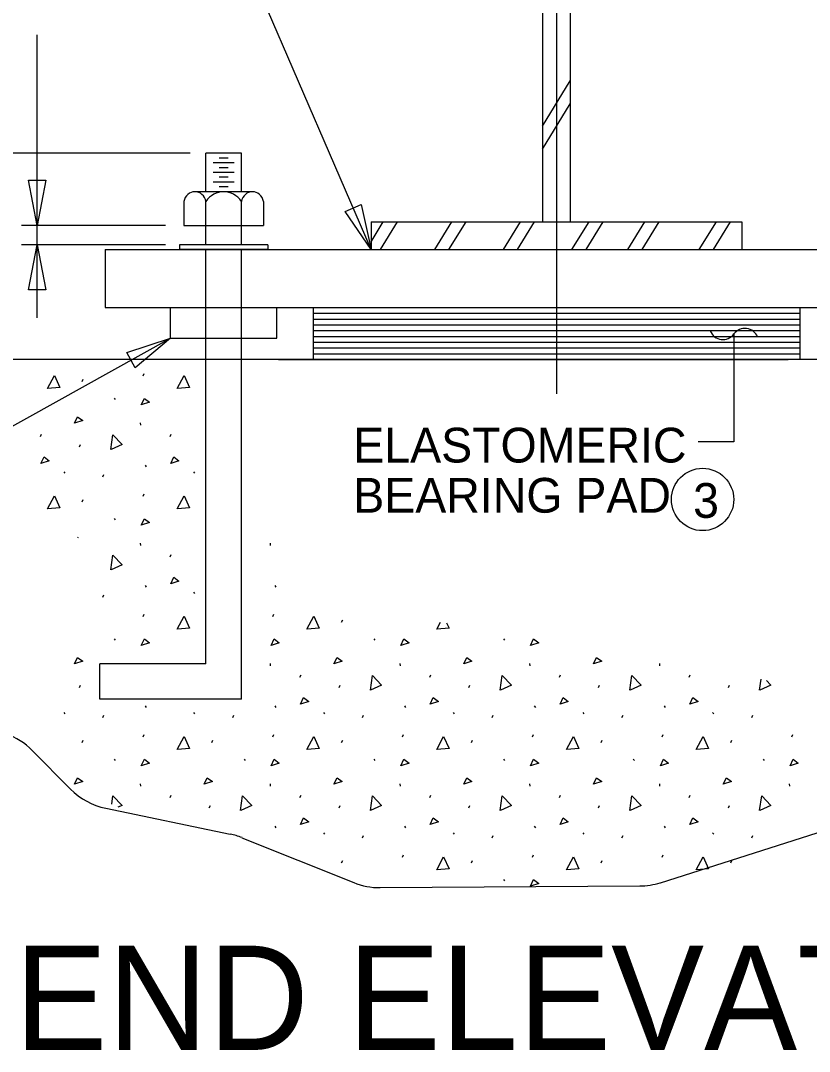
# Model space of a CAD drawing. Extents: x -125.5 to -89.4, y -5.1 to 16.9.
# Drawn here: x -118.408 to -115.571, y 10.484 to 14.192 of the extents above; entities that cross this region are included whole.
import ezdxf

# ---------------------------------------------------------------- set-up
doc = ezdxf.new("R2010")
doc.units = 0
for name, color, linetype in [('BR_AUTO DIMENSION', 7, 'Continuous'), ('BR_CENTER LINES', 7, 'Continuous'), ('BR_CONCRETE', 7, 'Continuous'), ('BR_REBAR', 7, 'Continuous'), ('BR_STRUCTURAL STEEL', 7, 'Continuous'), ('BR_TEXT', 7, 'Continuous'), ('Default', 7, 'Continuous')]:
    doc.layers.add(name, color=color, linetype=linetype)

msp = doc.modelspace()

# ---------------------------------------------------------------- linework, layer by layer
at = {"layer": 'BR_AUTO DIMENSION'}
for p, q in [((-117.1478, 13.3682), (-118.1091, 15.5991)), ((-118.3489, 13.1223), (-118.3489, 14.1408)), ((-117.7986, 13.7148), (-118.8938, 13.7148)), ((-117.8876, 13.4549), (-118.4049, 13.4549)), ((-117.8876, 13.3855), (-118.4049, 13.3855)), ((-115.8429, 13.0645), (-115.8429, 12.6766)), ((-119.3102, 12.2479), (-117.8689, 13.0491)), ((-115.8429, 12.6766), (-115.9716, 12.6766))]:
    msp.add_line(p, q, dxfattribs=at)
for points in [[(-118.3176, 13.6174), (-118.3489, 13.4549), (-118.3801, 13.6174)], [(-117.1834, 13.5298), (-117.1478, 13.3682), (-117.2408, 13.5051)], [(-118.3801, 13.223), (-118.3489, 13.3855), (-118.3176, 13.223)], [(-118.0261, 12.9975), (-117.8689, 13.0491), (-117.9957, 12.9429)]]:
    msp.add_lwpolyline(points, close=True, dxfattribs=at)
msp.add_circle((-115.9555, 12.4692), 0.1121, dxfattribs=at)
for centre, start, end in [((-115.8824, 13.0932), 201.5249, 323.9891), ((-115.8035, 13.0358), 21.5249, 143.9891)]:
    msp.add_arc(centre, 0.0488, start, end, dxfattribs=at)
at = {"layer": 'BR_CENTER LINES'}
msp.add_line((-116.4811, 15.9412), (-116.4811, 12.8489), dxfattribs=at)
at = {"layer": 'BR_CONCRETE'}
msp.add_line((-114.1549, 12.9727), (-119.7474, 12.9727), dxfattribs=at)
at = {"layer": 'BR_REBAR'}
for p, q in [((-117.6141, 13.7148), (-117.7415, 13.7148)), ((-117.7415, 13.5762), (-117.7415, 13.7148)), ((-117.6619, 13.6975), (-117.6937, 13.6975)), ((-117.6141, 13.5762), (-117.6141, 13.7148)), ((-117.6396, 13.6802), (-117.716, 13.6802)), ((-117.6619, 13.6628), (-117.6937, 13.6628)), ((-117.6396, 13.6455), (-117.716, 13.6455)), ((-117.6396, 13.6109), (-117.716, 13.6109)), ((-117.6619, 13.6282), (-117.6937, 13.6282)), ((-117.5743, 13.5762), (-117.7813, 13.5762)), ((-117.6619, 13.5935), (-117.6937, 13.5935)), ((-117.8211, 13.5415), (-117.8211, 13.4549)), ((-117.7415, 13.3855), (-117.7415, 13.5415)), ((-117.6141, 13.3855), (-117.6141, 13.5415)), ((-117.5345, 13.5415), (-117.5345, 13.4549)), ((-117.8211, 13.4549), (-117.5345, 13.4549)), ((-117.837, 13.3855), (-117.837, 13.3682)), ((-117.5185, 13.3855), (-117.837, 13.3855)), ((-117.5185, 13.3682), (-117.837, 13.3682)), ((-117.7415, 13.1599), (-117.7415, 13.3682)), ((-117.6141, 13.1599), (-117.6141, 13.3682)), ((-117.5185, 13.3855), (-117.5185, 13.3682)), ((-117.7415, 12.9727), (-117.7415, 13.1599)), ((-117.6141, 12.9727), (-117.6141, 13.1599)), ((-117.7415, 11.8779), (-117.7415, 12.9727)), ((-117.6141, 11.7505), (-117.6141, 12.9727)), ((-118.1234, 11.7505), (-118.1234, 11.8779)), ((-117.7415, 11.8779), (-118.1234, 11.8779)), ((-117.6141, 11.7505), (-118.1234, 11.7505))]:
    msp.add_line(p, q, dxfattribs=at)
for centre, major_axis, start_param, end_param in [((-117.7813, 13.5318), (0, 0.0444), 4.933703, 7.632667), ((-117.6778, 13.4895), (0, 0.0867), 5.35589, 7.210481), ((-117.5743, 13.5318), (0, 0.0444), 4.933703, 7.632667)]:
    msp.add_ellipse(centre, major_axis=major_axis, ratio=0.918783, start_param=start_param, end_param=end_param, dxfattribs=at)
at = {"layer": 'BR_STRUCTURAL STEEL'}
for p, q in [((-116.5311, 15.4006), (-116.5311, 13.4682)), ((-116.4311, 15.3403), (-116.4311, 13.4682)), ((-116.5311, 13.8126), (-116.4311, 13.9757)), ((-116.5311, 13.7298), (-116.4311, 13.8929)), ((-117.1478, 13.4682), (-115.8144, 13.4682)), ((-117.1478, 13.4682), (-117.1478, 13.3682)), ((-117.1478, 13.3963), (-117.1037, 13.4682)), ((-117.1143, 13.3682), (-117.0529, 13.4682)), ((-116.9184, 13.3682), (-116.8571, 13.4682)), ((-116.8677, 13.3682), (-116.8063, 13.4682)), ((-116.6718, 13.3682), (-116.6105, 13.4682)), ((-116.621, 13.3682), (-116.5597, 13.4682)), ((-116.4252, 13.3682), (-116.3638, 13.4682)), ((-116.3744, 13.3682), (-116.3131, 13.4682)), ((-116.224, 13.3682), (-116.1627, 13.4682)), ((-116.1732, 13.3682), (-116.1119, 13.4682)), ((-115.9672, 13.3682), (-115.9059, 13.4682)), ((-115.9164, 13.3682), (-115.8551, 13.4682)), ((-115.8144, 13.4682), (-115.8144, 13.3682)), ((-118.1036, 13.3682), (-114.8585, 13.3682)), ((-118.1036, 13.3682), (-118.1036, 13.1599)), ((-117.1478, 13.3682), (-115.8144, 13.3682)), ((-118.1036, 13.1599), (-114.8585, 13.1599)), ((-117.8689, 13.0491), (-117.8689, 13.1599)), ((-117.4867, 13.0491), (-117.4867, 13.1599)), ((-117.3561, 13.1599), (-117.3561, 12.9727)), ((-117.3561, 13.1391), (-115.6061, 13.1391)), ((-115.6061, 13.1599), (-115.6061, 12.9727)), ((-117.3561, 13.1183), (-115.6061, 13.1183)), ((-117.3561, 13.0975), (-115.6061, 13.0975)), ((-117.3561, 13.0767), (-115.6061, 13.0767)), ((-117.3561, 13.0559), (-115.6061, 13.0559)), ((-117.8689, 13.0491), (-117.4867, 13.0491)), ((-117.3561, 13.0351), (-115.6061, 13.0351)), ((-117.3561, 13.0143), (-115.6061, 13.0143)), ((-117.3561, 12.9935), (-115.6061, 12.9935))]:
    msp.add_line(p, q, dxfattribs=at)
at = {"layer": 'Default'}
for p, q in [((-117.3561, 13.1599), (-115.6061, 13.1599)), ((-117.4811, 12.9727), (-115.6478, 12.9727)), ((-118.3117, 12.8681), (-118.2868, 12.9153)), ((-118.2868, 12.9153), (-118.2673, 12.8718)), ((-117.9676, 12.9144), (-117.9639, 12.9227)), ((-117.8451, 12.8681), (-117.8201, 12.9153)), ((-117.8201, 12.9153), (-117.8007, 12.8718)), ((-118.2673, 12.8718), (-118.3108, 12.8681)), ((-118.1869, 12.8931), (-118.1831, 12.9014)), ((-117.8007, 12.8718), (-117.8441, 12.8681)), ((-118.0712, 12.8339), (-118.0675, 12.8283)), ((-117.9741, 12.8098), (-117.963, 12.833)), ((-117.963, 12.833), (-117.9445, 12.8191)), ((-117.9445, 12.8191), (-117.9741, 12.8098)), ((-118.2144, 12.7437), (-118.2033, 12.7668)), ((-118.2033, 12.7668), (-118.1848, 12.753)), ((-118.1848, 12.753), (-118.2144, 12.7437)), ((-117.9777, 12.7452), (-117.9768, 12.7368)), ((-118.3367, 12.6961), (-118.333, 12.7044)), ((-118.0836, 12.6486), (-118.0762, 12.7014)), ((-118.0762, 12.7014), (-118.0431, 12.6672)), ((-117.87, 12.6961), (-117.8663, 12.7044)), ((-118.1961, 12.6581), (-118.1924, 12.6665)), ((-118.0431, 12.6672), (-118.0827, 12.6489)), ((-118.3349, 12.5989), (-118.3238, 12.6221)), ((-118.3053, 12.6082), (-118.3349, 12.5989)), ((-118.3238, 12.6221), (-118.3053, 12.6082)), ((-117.8682, 12.5989), (-117.8571, 12.6221)), ((-117.8386, 12.6082), (-117.8682, 12.5989)), ((-117.8571, 12.6221), (-117.8386, 12.6082)), ((-117.9606, 12.5925), (-117.9569, 12.5869)), ((-118.2527, 12.5689), (-118.249, 12.5634)), ((-118.1119, 12.5508), (-118.1082, 12.5592)), ((-117.786, 12.5689), (-117.7823, 12.5634)), ((-118.3117, 12.4353), (-118.2868, 12.4824)), ((-118.2868, 12.4824), (-118.2673, 12.439)), ((-118.1869, 12.4602), (-118.1831, 12.4686)), ((-117.9676, 12.4815), (-117.9639, 12.4898)), ((-117.8451, 12.4353), (-117.8201, 12.4824)), ((-117.8201, 12.4824), (-117.8007, 12.439)), ((-118.2673, 12.439), (-118.3108, 12.4353)), ((-117.8007, 12.439), (-117.8441, 12.4353)), ((-118.0712, 12.401), (-118.0675, 12.3955)), ((-117.9741, 12.377), (-117.963, 12.4001)), ((-117.9445, 12.3862), (-117.9741, 12.377)), ((-117.963, 12.4001), (-117.9445, 12.3862)), ((-118.2037, 12.3332), (-118.2033, 12.334)), ((-118.2033, 12.334), (-118.2014, 12.3326)), ((-117.9777, 12.3123), (-117.9768, 12.304)), ((-117.511, 12.3123), (-117.5101, 12.304)), ((-118.0836, 12.2157), (-118.0762, 12.2686)), ((-118.0762, 12.2686), (-118.0431, 12.2344)), ((-117.87, 12.2632), (-117.8663, 12.2715)), ((-118.0431, 12.2344), (-118.0827, 12.216)), ((-117.8682, 12.1661), (-117.8571, 12.1892)), ((-117.8386, 12.1753), (-117.8682, 12.1661)), ((-117.8571, 12.1892), (-117.8386, 12.1753)), ((-118.1119, 12.118), (-118.1082, 12.1263)), ((-117.9606, 12.1596), (-117.9569, 12.1541)), ((-117.786, 12.1361), (-117.7823, 12.1305)), ((-117.4939, 12.1596), (-117.4902, 12.1541)), ((-117.9676, 12.0487), (-117.9639, 12.057)), ((-117.501, 12.0487), (-117.4973, 12.057)), ((-117.8451, 12.0024), (-117.8201, 12.0496)), ((-117.8201, 12.0496), (-117.8007, 12.0061)), ((-117.3784, 12.0024), (-117.3534, 12.0496)), ((-117.3534, 12.0496), (-117.334, 12.0061)), ((-117.2535, 12.0274), (-117.2498, 12.0357)), ((-116.9117, 12.0024), (-116.8983, 12.0278)), ((-116.8762, 12.026), (-116.8673, 12.0061)), ((-117.8007, 12.0061), (-117.8441, 12.0024)), ((-117.334, 12.0061), (-117.3775, 12.0024)), ((-116.8673, 12.0061), (-116.9108, 12.0024)), ((-118.0712, 11.9682), (-118.0675, 11.9627)), ((-117.9741, 11.9442), (-117.963, 11.9673)), ((-117.9445, 11.9534), (-117.9741, 11.9442)), ((-117.963, 11.9673), (-117.9445, 11.9534)), ((-117.5074, 11.9442), (-117.4963, 11.9673)), ((-117.4778, 11.9534), (-117.5074, 11.9442)), ((-117.4963, 11.9673), (-117.4778, 11.9534)), ((-117.1379, 11.9682), (-117.1342, 11.9627)), ((-117.0408, 11.9442), (-117.0297, 11.9673)), ((-117.0112, 11.9534), (-117.0408, 11.9442)), ((-117.0297, 11.9673), (-117.0112, 11.9534)), ((-116.6712, 11.9682), (-116.6675, 11.9627)), ((-116.5741, 11.9442), (-116.563, 11.9673)), ((-116.5445, 11.9534), (-116.5741, 11.9442)), ((-116.563, 11.9673), (-116.5445, 11.9534)), ((-118.2144, 11.878), (-118.2033, 11.9012)), ((-118.1848, 11.8873), (-118.2144, 11.878)), ((-118.2033, 11.9012), (-118.1848, 11.8873)), ((-117.511, 11.8795), (-117.5101, 11.8711)), ((-117.2811, 11.878), (-117.27, 11.9012)), ((-117.2515, 11.8873), (-117.2811, 11.878)), ((-117.27, 11.9012), (-117.2515, 11.8873)), ((-117.0444, 11.8795), (-117.0434, 11.8711)), ((-116.8144, 11.878), (-116.8033, 11.9012)), ((-116.7848, 11.8873), (-116.8144, 11.878)), ((-116.8033, 11.9012), (-116.7848, 11.8873)), ((-116.5777, 11.8795), (-116.5768, 11.8711)), ((-116.3478, 11.878), (-116.3367, 11.9012)), ((-116.3182, 11.8873), (-116.3478, 11.878)), ((-116.3367, 11.9012), (-116.3182, 11.8873)), ((-116.111, 11.8795), (-116.1101, 11.8711)), ((-117.4034, 11.8304), (-117.3997, 11.8387)), ((-117.1502, 11.7829), (-117.1429, 11.8357)), ((-117.1429, 11.8357), (-117.1098, 11.8015)), ((-116.9367, 11.8304), (-116.933, 11.8387)), ((-116.6836, 11.7829), (-116.6762, 11.8357)), ((-116.6762, 11.8357), (-116.6431, 11.8015)), ((-116.47, 11.8304), (-116.4663, 11.8387)), ((-116.2169, 11.7829), (-116.2096, 11.8357)), ((-116.2096, 11.8357), (-116.1764, 11.8015)), ((-116.0034, 11.8304), (-115.9997, 11.8387)), ((-118.1961, 11.7924), (-118.1924, 11.8008)), ((-117.2628, 11.7924), (-117.2591, 11.8008)), ((-117.1098, 11.8015), (-117.1494, 11.7832)), ((-116.7961, 11.7924), (-116.7924, 11.8008)), ((-116.6431, 11.8015), (-116.6827, 11.7832)), ((-116.3294, 11.7924), (-116.3257, 11.8008)), ((-116.1764, 11.8015), (-116.216, 11.7832)), ((-115.8628, 11.7924), (-115.8591, 11.8008)), ((-115.7502, 11.7829), (-115.7446, 11.8233)), ((-115.7098, 11.8015), (-115.7494, 11.7832)), ((-115.7256, 11.8179), (-115.7098, 11.8015)), ((-117.4015, 11.7332), (-117.3904, 11.7564)), ((-117.3904, 11.7564), (-117.3719, 11.7425)), ((-116.9349, 11.7332), (-116.9238, 11.7564)), ((-116.9238, 11.7564), (-116.9053, 11.7425)), ((-116.4682, 11.7332), (-116.4571, 11.7564)), ((-116.4571, 11.7564), (-116.4386, 11.7425)), ((-116.0015, 11.7332), (-115.9904, 11.7564)), ((-115.9904, 11.7564), (-115.9719, 11.7425)), ((-117.9606, 11.7268), (-117.9569, 11.7212)), ((-117.4939, 11.7268), (-117.4902, 11.7212)), ((-117.3719, 11.7425), (-117.4015, 11.7332)), ((-117.0273, 11.7268), (-117.0236, 11.7212)), ((-116.9053, 11.7425), (-116.9349, 11.7332)), ((-116.5606, 11.7268), (-116.5569, 11.7212)), ((-116.4386, 11.7425), (-116.4682, 11.7332)), ((-116.0939, 11.7268), (-116.0902, 11.7212)), ((-115.9719, 11.7425), (-116.0015, 11.7332)), ((-118.2527, 11.7033), (-118.249, 11.6977)), ((-118.1119, 11.6852), (-118.1082, 11.6935)), ((-117.786, 11.7033), (-117.7823, 11.6977)), ((-117.6453, 11.6852), (-117.6416, 11.6935)), ((-117.3193, 11.7033), (-117.3156, 11.6977)), ((-117.1786, 11.6852), (-117.1749, 11.6935)), ((-116.8527, 11.7033), (-116.849, 11.6977)), ((-116.7119, 11.6852), (-116.7082, 11.6935)), ((-116.386, 11.7033), (-116.3823, 11.6977)), ((-116.2453, 11.6852), (-116.2416, 11.6935)), ((-115.9193, 11.7033), (-115.9156, 11.6977)), ((-115.7786, 11.6852), (-115.7749, 11.6935)), ((-117.9676, 11.6158), (-117.9639, 11.6242)), ((-117.8451, 11.5696), (-117.8201, 11.6168)), ((-117.8201, 11.6168), (-117.8007, 11.5733)), ((-117.501, 11.6158), (-117.4973, 11.6242)), ((-117.3784, 11.5696), (-117.3534, 11.6168)), ((-117.3534, 11.6168), (-117.334, 11.5733)), ((-117.0343, 11.6158), (-117.0306, 11.6242)), ((-116.9117, 11.5696), (-116.8868, 11.6168)), ((-116.8868, 11.6168), (-116.8673, 11.5733)), ((-116.5676, 11.6158), (-116.5639, 11.6242)), ((-116.4451, 11.5696), (-116.4201, 11.6168)), ((-116.4201, 11.6168), (-116.4007, 11.5733)), ((-116.101, 11.6158), (-116.0973, 11.6242)), ((-115.9784, 11.5696), (-115.9534, 11.6168)), ((-115.9534, 11.6168), (-115.934, 11.5733)), ((-115.6343, 11.6158), (-115.6306, 11.6242)), ((-118.1869, 11.5946), (-118.1831, 11.6029)), ((-117.8007, 11.5733), (-117.8441, 11.5696)), ((-117.7202, 11.5946), (-117.7165, 11.6029)), ((-117.334, 11.5733), (-117.3775, 11.5696)), ((-117.2535, 11.5946), (-117.2498, 11.6029)), ((-116.8673, 11.5733), (-116.9108, 11.5696)), ((-116.7869, 11.5946), (-116.7831, 11.6029)), ((-116.4007, 11.5733), (-116.4441, 11.5696)), ((-116.3202, 11.5946), (-116.3165, 11.6029)), ((-115.934, 11.5733), (-115.9775, 11.5696)), ((-115.8535, 11.5946), (-115.8498, 11.6029)), ((-118.366, 11.5661), (-118.2288, 11.4273)), ((-118.0712, 11.5354), (-118.0675, 11.5298)), ((-117.9741, 11.5113), (-117.963, 11.5344)), ((-117.963, 11.5344), (-117.9445, 11.5206)), ((-117.6046, 11.5354), (-117.6009, 11.5298)), ((-117.5074, 11.5113), (-117.4963, 11.5344)), ((-117.4963, 11.5344), (-117.4778, 11.5206)), ((-117.1379, 11.5354), (-117.1342, 11.5298)), ((-117.0408, 11.5113), (-117.0297, 11.5344)), ((-117.0297, 11.5344), (-117.0112, 11.5206)), ((-116.6712, 11.5354), (-116.6675, 11.5298)), ((-116.5741, 11.5113), (-116.563, 11.5344)), ((-116.563, 11.5344), (-116.5445, 11.5206)), ((-116.2046, 11.5354), (-116.2009, 11.5298)), ((-116.1074, 11.5113), (-116.0963, 11.5344)), ((-116.0963, 11.5344), (-116.0778, 11.5206)), ((-115.7379, 11.5354), (-115.7342, 11.5298)), ((-115.6408, 11.5113), (-115.6297, 11.5344)), ((-115.6297, 11.5344), (-115.6112, 11.5206)), ((-117.9445, 11.5206), (-117.9741, 11.5113)), ((-117.4778, 11.5206), (-117.5074, 11.5113)), ((-117.0112, 11.5206), (-117.0408, 11.5113)), ((-116.5445, 11.5206), (-116.5741, 11.5113)), ((-116.0778, 11.5206), (-116.1074, 11.5113)), ((-115.6112, 11.5206), (-115.6408, 11.5113)), ((-118.2144, 11.4452), (-118.2033, 11.4683)), ((-118.2033, 11.4683), (-118.1848, 11.4544)), ((-117.7478, 11.4452), (-117.7367, 11.4683)), ((-117.7367, 11.4683), (-117.7182, 11.4544)), ((-117.2811, 11.4452), (-117.27, 11.4683)), ((-117.27, 11.4683), (-117.2515, 11.4544)), ((-116.8144, 11.4452), (-116.8033, 11.4683)), ((-116.8033, 11.4683), (-116.7848, 11.4544)), ((-116.3478, 11.4452), (-116.3367, 11.4683)), ((-116.3367, 11.4683), (-116.3182, 11.4544)), ((-115.8811, 11.4452), (-115.87, 11.4683)), ((-115.87, 11.4683), (-115.8515, 11.4544)), ((-118.1848, 11.4544), (-118.2144, 11.4452)), ((-117.9777, 11.4466), (-117.9768, 11.4383)), ((-117.7182, 11.4544), (-117.7478, 11.4452)), ((-117.511, 11.4466), (-117.5101, 11.4383)), ((-117.2515, 11.4544), (-117.2811, 11.4452)), ((-117.0444, 11.4466), (-117.0434, 11.4383)), ((-116.7848, 11.4544), (-116.8144, 11.4452)), ((-116.5777, 11.4466), (-116.5768, 11.4383)), ((-116.3182, 11.4544), (-116.3478, 11.4452)), ((-116.111, 11.4466), (-116.1101, 11.4383)), ((-115.8515, 11.4544), (-115.8811, 11.4452)), ((-115.6444, 11.4466), (-115.6434, 11.4383)), ((-118.0803, 11.3735), (-118.0762, 11.4029)), ((-118.0762, 11.4029), (-118.0431, 11.3687)), ((-117.87, 11.3975), (-117.8663, 11.4059)), ((-117.6169, 11.35), (-117.6096, 11.4029)), ((-117.6096, 11.4029), (-117.5764, 11.3687)), ((-117.4034, 11.3975), (-117.3997, 11.4059)), ((-117.1502, 11.35), (-117.1429, 11.4029)), ((-117.1429, 11.4029), (-117.1098, 11.3687)), ((-116.9367, 11.3975), (-116.933, 11.4059)), ((-116.6836, 11.35), (-116.6762, 11.4029)), ((-116.6762, 11.4029), (-116.6431, 11.3687)), ((-116.47, 11.3975), (-116.4663, 11.4059)), ((-116.2169, 11.35), (-116.2096, 11.4029)), ((-116.2096, 11.4029), (-116.1764, 11.3687)), ((-116.0034, 11.3975), (-115.9997, 11.4059)), ((-115.7502, 11.35), (-115.7429, 11.4029)), ((-115.7429, 11.4029), (-115.7098, 11.3687)), ((-118.1017, 11.3582), (-117.6544, 11.2655)), ((-118.0431, 11.3687), (-118.058, 11.3618)), ((-117.7294, 11.3596), (-117.7257, 11.3679)), ((-117.5764, 11.3687), (-117.616, 11.3503)), ((-117.2628, 11.3596), (-117.2591, 11.3679)), ((-117.1098, 11.3687), (-117.1494, 11.3503)), ((-116.7961, 11.3596), (-116.7924, 11.3679)), ((-116.6431, 11.3687), (-116.6827, 11.3503)), ((-116.3294, 11.3596), (-116.3257, 11.3679)), ((-116.1764, 11.3687), (-116.216, 11.3503)), ((-115.8628, 11.3596), (-115.8591, 11.3679)), ((-115.7098, 11.3687), (-115.7494, 11.3503)), ((-117.4015, 11.3004), (-117.3904, 11.3235)), ((-117.3719, 11.3097), (-117.4015, 11.3004)), ((-117.3904, 11.3235), (-117.3719, 11.3097)), ((-116.9349, 11.3004), (-116.9238, 11.3235)), ((-116.9053, 11.3097), (-116.9349, 11.3004)), ((-116.9238, 11.3235), (-116.9053, 11.3097)), ((-116.4682, 11.3004), (-116.4571, 11.3235)), ((-116.4386, 11.3097), (-116.4682, 11.3004)), ((-116.4571, 11.3235), (-116.4386, 11.3097)), ((-116.1074, 11.0907), (-115.4053, 11.3142)), ((-116.0015, 11.3004), (-115.9904, 11.3235)), ((-115.9719, 11.3097), (-116.0015, 11.3004)), ((-115.9904, 11.3235), (-115.9719, 11.3097)), ((-117.4939, 11.294), (-117.4902, 11.2884)), ((-117.0273, 11.294), (-117.0236, 11.2884)), ((-116.5606, 11.294), (-116.5569, 11.2884)), ((-116.0939, 11.294), (-116.0902, 11.2884)), ((-117.6119, 11.2526), (-117.2101, 11.0909)), ((-117.3193, 11.2704), (-117.3156, 11.2649)), ((-117.1786, 11.2523), (-117.1749, 11.2606)), ((-116.8527, 11.2704), (-116.849, 11.2649)), ((-116.7119, 11.2523), (-116.7082, 11.2606)), ((-116.386, 11.2704), (-116.3823, 11.2649)), ((-116.2453, 11.2523), (-116.2416, 11.2606)), ((-115.9193, 11.2704), (-115.9156, 11.2649)), ((-115.7786, 11.2523), (-115.7749, 11.2606)), ((-117.2535, 11.1617), (-117.2498, 11.17)), ((-117.0343, 11.183), (-117.0306, 11.1913)), ((-116.9117, 11.1367), (-116.8868, 11.1839)), ((-116.8868, 11.1839), (-116.8673, 11.1404)), ((-116.7869, 11.1617), (-116.7831, 11.17)), ((-116.5676, 11.183), (-116.5639, 11.1913)), ((-116.4451, 11.1367), (-116.4201, 11.1839)), ((-116.4201, 11.1839), (-116.4007, 11.1404)), ((-116.3202, 11.1617), (-116.3165, 11.17)), ((-116.101, 11.183), (-116.0973, 11.1913)), ((-115.9784, 11.1367), (-115.9534, 11.1839)), ((-115.9534, 11.1839), (-115.934, 11.1404)), ((-115.8535, 11.1617), (-115.8498, 11.17)), ((-116.8673, 11.1404), (-116.9108, 11.1367)), ((-116.4007, 11.1404), (-116.4441, 11.1367)), ((-115.934, 11.1404), (-115.9775, 11.1367)), ((-116.6712, 11.1025), (-116.6675, 11.097)), ((-116.5741, 11.0785), (-116.563, 11.1016)), ((-116.5445, 11.0877), (-116.5741, 11.0785)), ((-116.563, 11.1016), (-116.5445, 11.0877)), ((-117.1152, 11.0729), (-116.1817, 11.0789))]:
    msp.add_line(p, q, dxfattribs=at)
for centre, start, end in [((-118.5438, 11.3904), 44.6646, 70.5152), ((-118.051, 11.603), 224.6646, 258.2842), ((-117.7052, 11.0207), 68.0825, 78.2842), ((-117.1168, 11.3229), 248.0825, 270.3686), ((-116.1833, 11.3289), 270.3686, 287.6557)]:
    msp.add_arc(centre, 0.25, start, end, dxfattribs=at)

# ---------------------------------------------------------------- texts
at = {"layer": 'BR_AUTO DIMENSION'}
for s, p in [('ELASTOMERIC', (-117.2116, 12.6022)), ('BEARING PAD', (-117.2116, 12.4217)), ('3', (-115.9895, 12.4032))]:
    msp.add_text(s, height=0.125, dxfattribs=at).set_placement(p)
at = {"layer": 'BR_TEXT'}
msp.add_text('END ELEVATION', height=0.375, dxfattribs=at).set_placement((-118.4304, 10.4891))

doc.saveas('drawing.dxf')
